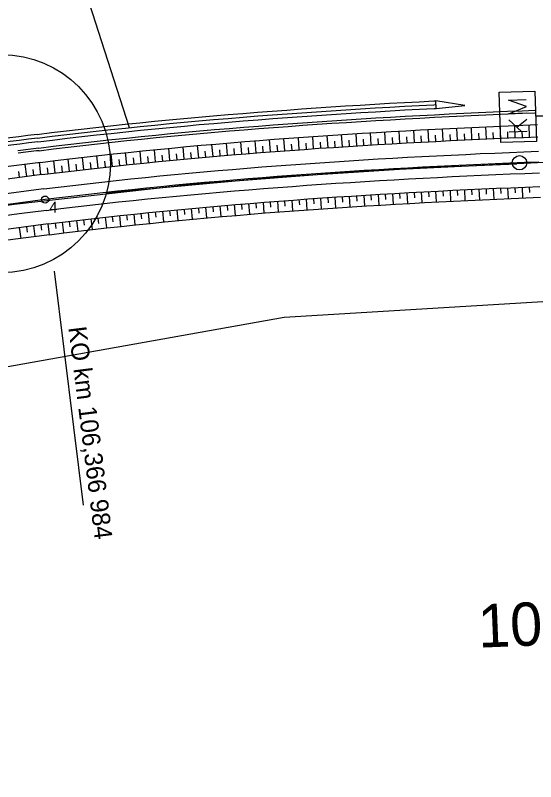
# Model space of a CAD drawing. Extents: x -759005 to -757278, y -1175311 to -1173953.
# Drawn here: x -758243.6 to -758207.5, y -1174807.5 to -1174754.3 of the extents above; entities that cross this region are included whole.
import ezdxf

# ---------------------------------------------------------------- set-up
doc = ezdxf.new("R2010")
doc.units = 0
for name, color, linetype in [('_NOR-návrh tenká', 7, 'Continuous'), ('_NOR-osa', 7, 'Continuous'), ('_NOR-popis', 7, 'Continuous'), ('_NOR-svahy', 7, 'Continuous'), ('_NOR-vytyčení', 7, 'Continuous'), ('G_Obvod stavby', 7, 'Continuous'), ('Vrstva 1', 7, 'Continuous'), ('Vrstva 52', 7, 'Continuous'), ('Vrstva 7', 7, 'Continuous')]:
    doc.layers.add(name, color=color, linetype=linetype)

# ---------------------------------------------------------------- blocks, each defined once
blk = doc.blocks.new('C020')
at = {"layer": 'Vrstva 7'}
for p, q in [((-1.017, 2.489), (-1.017, 1.242)), ((-0.182, 2.489), (-1.017, 1.654)), ((-0.713, 1.959), (-0.182, 1.242)), ((0, 0), (0, 0.623))]:
    blk.add_line(p, q, dxfattribs=at)
blk.add_lwpolyline([(-1.742, 0.623), (-1.742, 3.106), (1.746, 3.106), (1.746, 0.623)], close=True, dxfattribs=at)
blk.add_lwpolyline([(0.23, 1.242), (0.23, 2.489), (0.711, 1.242), (1.182, 2.489), (1.182, 1.242)], dxfattribs=at)
blk = doc.blocks.new('POINT_DISPLAY')
blk.add_line((0, 0), (0, 0))

msp = doc.modelspace()

# ---------------------------------------------------------------- linework, layer by layer
at = {"layer": '_NOR-návrh tenká'}
for p, q in [((-758214.421, -1174760.78), (-758214.447, -1174760.26)), ((-758212.435, -1174760.572), (-758214.447, -1174760.26)), ((-758214.421, -1174760.78), (-758212.435, -1174760.572))]:
    msp.add_line(p, q, dxfattribs=at)
for points in [[(-758242.105, -1174762.587), (-758241.09, -1174762.463), (-758240.072, -1174762.341), (-758239.053, -1174762.223), (-758238.033, -1174762.108), (-758237.014, -1174761.997), (-758235.995, -1174761.888), (-758234.975, -1174761.783), (-758233.956, -1174761.681), (-758232.936, -1174761.583), (-758231.917, -1174761.487), (-758230.897, -1174761.394), (-758229.877, -1174761.304), (-758228.858, -1174761.217), (-758227.838, -1174761.133), (-758226.819, -1174761.052), (-758225.799, -1174760.973), (-758224.78, -1174760.897), (-758223.76, -1174760.823), (-758222.741, -1174760.752), (-758221.722, -1174760.684), (-758220.703, -1174760.617), (-758219.684, -1174760.554), (-758218.665, -1174760.492), (-758217.646, -1174760.433), (-758216.627, -1174760.375), (-758215.609, -1174760.32), (-758214.59, -1174760.267), (-758214.447, -1174760.26)], [(-758242.073, -1174762.845), (-758241.059, -1174762.721), (-758240.041, -1174762.599), (-758239.023, -1174762.481), (-758238.005, -1174762.366), (-758236.986, -1174762.255), (-758235.968, -1174762.147), (-758234.949, -1174762.042), (-758233.93, -1174761.94), (-758232.912, -1174761.842), (-758231.893, -1174761.746), (-758230.874, -1174761.653), (-758229.855, -1174761.563), (-758228.836, -1174761.476), (-758227.817, -1174761.392), (-758226.798, -1174761.311), (-758225.78, -1174761.232), (-758224.761, -1174761.156), (-758223.742, -1174761.083), (-758222.723, -1174761.012), (-758221.705, -1174760.943), (-758220.686, -1174760.877), (-758219.668, -1174760.813), (-758218.649, -1174760.752), (-758217.631, -1174760.692), (-758216.613, -1174760.635), (-758215.595, -1174760.58), (-758214.577, -1174760.527), (-758214.434, -1174760.52)], [(-758242.041, -1174763.103), (-758241.028, -1174762.979), (-758240.011, -1174762.857), (-758238.994, -1174762.739), (-758237.976, -1174762.625), (-758236.958, -1174762.514), (-758235.941, -1174762.406), (-758234.923, -1174762.301), (-758233.905, -1174762.199), (-758232.887, -1174762.1), (-758231.869, -1174762.005), (-758230.851, -1174761.912), (-758229.833, -1174761.822), (-758228.814, -1174761.736), (-758227.796, -1174761.651), (-758226.778, -1174761.57), (-758225.76, -1174761.491), (-758224.742, -1174761.415), (-758223.724, -1174761.342), (-758222.705, -1174761.271), (-758221.687, -1174761.202), (-758220.67, -1174761.136), (-758219.652, -1174761.073), (-758218.634, -1174761.011), (-758217.616, -1174760.952), (-758216.599, -1174760.895), (-758215.581, -1174760.84), (-758214.564, -1174760.787), (-758214.421, -1174760.78)], [(-758241.988, -1174763.537), (-758240.975, -1174763.413), (-758239.96, -1174763.291), (-758238.944, -1174763.174), (-758237.928, -1174763.059), (-758236.912, -1174762.948), (-758235.895, -1174762.84), (-758234.879, -1174762.735), (-758233.862, -1174762.634), (-758232.845, -1174762.535), (-758231.829, -1174762.44), (-758230.812, -1174762.347), (-758229.795, -1174762.258), (-758228.778, -1174762.171), (-758227.761, -1174762.087), (-758226.744, -1174762.006), (-758225.727, -1174761.927), (-758224.71, -1174761.851), (-758223.693, -1174761.778), (-758222.676, -1174761.707), (-758221.659, -1174761.639), (-758220.642, -1174761.572), (-758219.625, -1174761.509), (-758218.608, -1174761.447), (-758217.591, -1174761.388), (-758216.575, -1174761.331), (-758215.558, -1174761.276), (-758214.542, -1174761.223), (-758213.525, -1174761.172), (-758212.509, -1174761.123), (-758211.493, -1174761.076), (-758210.477, -1174761.031), (-758209.461, -1174760.987), (-758208.445, -1174760.945), (-758207.581, -1174760.911)], [(-758241.966, -1174763.716), (-758240.954, -1174763.591), (-758239.939, -1174763.47), (-758238.923, -1174763.352), (-758237.908, -1174763.238), (-758236.892, -1174763.127), (-758235.877, -1174763.019), (-758234.861, -1174762.915), (-758233.845, -1174762.813), (-758232.828, -1174762.715), (-758231.812, -1174762.619), (-758230.796, -1174762.527), (-758229.779, -1174762.437), (-758228.763, -1174762.35), (-758227.746, -1174762.266), (-758226.73, -1174762.185), (-758225.713, -1174762.107), (-758224.696, -1174762.031), (-758223.68, -1174761.957), (-758222.663, -1174761.887), (-758221.647, -1174761.818), (-758220.63, -1174761.752), (-758219.614, -1174761.688), (-758218.597, -1174761.627), (-758217.581, -1174761.568), (-758216.565, -1174761.511), (-758215.548, -1174761.456), (-758214.532, -1174761.403), (-758213.516, -1174761.352), (-758212.5, -1174761.303), (-758211.484, -1174761.256), (-758210.469, -1174761.211), (-758209.453, -1174761.167), (-758208.438, -1174761.125), (-758207.573, -1174761.091)], [(-758241.865, -1174764.529), (-758240.855, -1174764.405), (-758239.843, -1174764.285), (-758238.83, -1174764.167), (-758237.818, -1174764.053), (-758236.804, -1174763.942), (-758235.791, -1174763.835), (-758234.778, -1174763.73), (-758233.764, -1174763.629), (-758232.75, -1174763.531), (-758231.737, -1174763.436), (-758230.723, -1174763.343), (-758229.708, -1174763.254), (-758228.694, -1174763.168), (-758227.68, -1174763.084), (-758226.665, -1174763.003), (-758225.651, -1174762.924), (-758224.636, -1174762.849), (-758223.622, -1174762.775), (-758222.607, -1174762.705), (-758221.593, -1174762.636), (-758220.578, -1174762.57), (-758219.563, -1174762.507), (-758218.549, -1174762.446), (-758217.534, -1174762.386), (-758216.52, -1174762.33), (-758215.505, -1174762.275), (-758214.49, -1174762.222), (-758213.476, -1174762.171), (-758212.462, -1174762.122), (-758211.447, -1174762.075), (-758210.433, -1174762.03), (-758209.419, -1174761.986), (-758208.404, -1174761.945), (-758207.39, -1174761.905)], [(-758241.761, -1174765.373), (-758240.753, -1174765.249), (-758239.744, -1174765.129), (-758238.734, -1174765.012), (-758237.724, -1174764.898), (-758236.713, -1174764.787), (-758235.703, -1174764.68), (-758234.692, -1174764.576), (-758233.681, -1174764.475), (-758232.67, -1174764.377), (-758231.658, -1174764.282), (-758230.647, -1174764.19), (-758229.635, -1174764.101), (-758228.623, -1174764.015), (-758227.611, -1174763.931), (-758226.599, -1174763.85), (-758225.587, -1174763.772), (-758224.574, -1174763.696), (-758223.562, -1174763.623), (-758222.549, -1174763.553), (-758221.537, -1174763.485), (-758220.524, -1174763.419), (-758219.511, -1174763.355), (-758218.498, -1174763.294), (-758217.486, -1174763.235), (-758216.473, -1174763.178), (-758215.46, -1174763.123), (-758214.447, -1174763.071), (-758213.434, -1174763.02), (-758212.421, -1174762.971), (-758211.409, -1174762.924), (-758210.396, -1174762.879), (-758209.383, -1174762.836), (-758208.37, -1174762.794), (-758207.357, -1174762.754)], [(-758241.638, -1174766.365), (-758240.633, -1174766.242), (-758239.627, -1174766.122), (-758238.62, -1174766.005), (-758237.613, -1174765.892), (-758236.606, -1174765.782), (-758235.599, -1174765.675), (-758234.591, -1174765.571), (-758233.583, -1174765.47), (-758232.575, -1174765.373), (-758231.566, -1174765.278), (-758230.558, -1174765.186), (-758229.549, -1174765.097), (-758228.539, -1174765.011), (-758227.53, -1174764.928), (-758226.521, -1174764.847), (-758225.511, -1174764.769), (-758224.501, -1174764.694), (-758223.491, -1174764.621), (-758222.481, -1174764.55), (-758221.471, -1174764.482), (-758220.46, -1174764.417), (-758219.45, -1174764.353), (-758218.439, -1174764.292), (-758217.429, -1174764.233), (-758216.418, -1174764.177), (-758215.407, -1174764.122), (-758214.396, -1174764.069), (-758213.385, -1174764.019), (-758212.374, -1174763.97), (-758211.363, -1174763.923), (-758210.352, -1174763.878), (-758209.341, -1174763.835), (-758208.33, -1174763.793), (-758207.319, -1174763.753)], [(-758241.454, -1174767.854), (-758240.453, -1174767.731), (-758239.452, -1174767.612), (-758238.45, -1174767.496), (-758237.448, -1174767.383), (-758236.446, -1174767.273), (-758235.443, -1174767.167), (-758234.44, -1174767.063), (-758233.436, -1174766.963), (-758232.432, -1174766.866), (-758231.428, -1174766.771), (-758230.424, -1174766.68), (-758229.419, -1174766.592), (-758228.414, -1174766.506), (-758227.409, -1174766.423), (-758226.403, -1174766.342), (-758225.397, -1174766.265), (-758224.391, -1174766.19), (-758223.385, -1174766.117), (-758222.378, -1174766.047), (-758221.372, -1174765.979), (-758220.365, -1174765.914), (-758219.358, -1174765.851), (-758218.35, -1174765.79), (-758217.343, -1174765.731), (-758216.335, -1174765.674), (-758215.328, -1174765.62), (-758214.32, -1174765.567), (-758213.312, -1174765.517), (-758212.303, -1174765.468), (-758211.295, -1174765.422), (-758210.287, -1174765.377), (-758209.278, -1174765.333), (-758208.269, -1174765.292), (-758207.261, -1174765.252)], [(-758241.337, -1174768.797), (-758240.338, -1174768.674), (-758239.341, -1174768.555), (-758238.342, -1174768.439), (-758237.343, -1174768.327), (-758236.344, -1174768.218), (-758235.344, -1174768.111), (-758234.344, -1174768.008), (-758233.343, -1174767.908), (-758232.342, -1174767.811), (-758231.341, -1174767.717), (-758230.339, -1174767.626), (-758229.337, -1174767.538), (-758228.334, -1174767.452), (-758227.332, -1174767.37), (-758226.329, -1174767.29), (-758225.325, -1174767.212), (-758224.322, -1174767.137), (-758223.318, -1174767.065), (-758222.313, -1174766.995), (-758221.309, -1174766.927), (-758220.304, -1174766.862), (-758219.299, -1174766.799), (-758218.294, -1174766.738), (-758217.289, -1174766.679), (-758216.283, -1174766.623), (-758215.277, -1174766.569), (-758214.271, -1174766.516), (-758213.265, -1174766.466), (-758212.258, -1174766.417), (-758211.252, -1174766.371), (-758210.245, -1174766.326), (-758209.238, -1174766.283), (-758208.231, -1174766.241), (-758207.224, -1174766.201)], [(-758241.245, -1174769.541), (-758240.248, -1174769.419), (-758239.253, -1174769.3), (-758238.257, -1174769.185), (-758237.26, -1174769.072), (-758236.263, -1174768.963), (-758235.266, -1174768.857), (-758234.268, -1174768.755), (-758233.27, -1174768.655), (-758232.271, -1174768.558), (-758231.272, -1174768.464), (-758230.272, -1174768.373), (-758229.272, -1174768.285), (-758228.272, -1174768.2), (-758227.271, -1174768.117), (-758226.27, -1174768.037), (-758225.268, -1174767.96), (-758224.267, -1174767.885), (-758223.265, -1174767.813), (-758222.262, -1174767.743), (-758221.259, -1174767.675), (-758220.256, -1174767.61), (-758219.253, -1174767.547), (-758218.25, -1174767.487), (-758217.246, -1174767.428), (-758216.242, -1174767.372), (-758215.237, -1174767.318), (-758214.233, -1174767.265), (-758213.228, -1174767.215), (-758212.223, -1174767.166), (-758211.218, -1174767.12), (-758210.212, -1174767.075), (-758209.207, -1174767.032), (-758208.201, -1174766.991), (-758207.195, -1174766.951)]]:
    msp.add_lwpolyline(points, dxfattribs=at)
for radius, start, end in [(297.557, 97.09744, 101.02201), (297.297, 97.09748, 101.02201), (297.037, 97.09752, 101.02201), (296.6, 97.09759, 97.37991), (296.42, 97.09762, 97.38099), (295.6, 97.09776, 129.28488), (294.75, 97.0979, 129.28474), (293.75, 97.09807, 120.96729), (292.25, 97.09832, 120.96729), (291.3, 97.09848, 129.28417), (290.55, 97.09861, 129.28404)]:
    msp.add_arc((-758205.34, -1175057.864), radius, start, end, dxfattribs=at)
at = {"layer": '_NOR-osa'}
msp.add_lwpolyline([(-758207.29, -1174764.503), (-758208.3, -1174764.543), (-758209.31, -1174764.584), (-758210.319, -1174764.627), (-758211.329, -1174764.672), (-758212.339, -1174764.719), (-758213.348, -1174764.768), (-758214.358, -1174764.818), (-758215.367, -1174764.871), (-758216.377, -1174764.926), (-758217.386, -1174764.982), (-758218.395, -1174765.041), (-758219.404, -1174765.102), (-758220.412, -1174765.165), (-758221.421, -1174765.231), (-758222.43, -1174765.299), (-758223.438, -1174765.369), (-758224.446, -1174765.442), (-758225.454, -1174765.517), (-758226.462, -1174765.595), (-758227.469, -1174765.675), (-758228.477, -1174765.758), (-758229.484, -1174765.844), (-758230.491, -1174765.933), (-758231.497, -1174766.025), (-758232.504, -1174766.119), (-758233.51, -1174766.217), (-758234.515, -1174766.317), (-758235.521, -1174766.421), (-758236.526, -1174766.527), (-758237.531, -1174766.637), (-758238.535, -1174766.75), (-758239.539, -1174766.867), (-758240.543, -1174766.987), (-758241.546, -1174767.11)], dxfattribs=at)
msp.add_circle((-758241.546, -1174767.11), 0.25, dxfattribs=at)
msp.add_arc((-758205.34, -1175057.864), 293, 97.09819, 129.28445, dxfattribs=at)
at = {"layer": '_NOR-popis'}
msp.add_line((-758240.928, -1174772.071), (-758238.907, -1174788.304), dxfattribs=at)
msp.add_lwpolyline([(-758240.814, -1174715.275), (-758249.857, -1174718.187), (-758235.706, -1174762.12)], dxfattribs=at)
msp.add_circle((-758208.639, -1174764.556), 0.5, dxfattribs=at)
at = {"layer": '_NOR-svahy'}
for points in [[(-758213.935, -1174763.045), (-758213.977, -1174762.196)], [(-758212.936, -1174762.996), (-758212.977, -1174762.147)], [(-758211.937, -1174762.949), (-758211.976, -1174762.1)], [(-758210.938, -1174762.903), (-758210.976, -1174762.054)], [(-758209.939, -1174762.859), (-758209.975, -1174762.01)], [(-758208.94, -1174762.817), (-758208.975, -1174761.968)], [(-758207.941, -1174762.777), (-758207.974, -1174761.928)], [(-758222.919, -1174763.578), (-758222.978, -1174762.73)], [(-758221.921, -1174763.51), (-758221.978, -1174762.662)], [(-758220.923, -1174763.445), (-758220.978, -1174762.596)], [(-758219.925, -1174763.381), (-758219.978, -1174762.533)], [(-758218.927, -1174763.32), (-758218.978, -1174762.472)], [(-758217.929, -1174763.261), (-758217.978, -1174762.412)], [(-758216.93, -1174763.204), (-758216.978, -1174762.355)], [(-758216.431, -1174763.176), (-758216.454, -1174762.752)], [(-758215.932, -1174763.149), (-758215.978, -1174762.3)], [(-758215.433, -1174763.122), (-758215.455, -1174762.698)], [(-758214.933, -1174763.096), (-758214.977, -1174762.247)], [(-758214.434, -1174763.07), (-758214.455, -1174762.646)], [(-758213.435, -1174763.02), (-758213.457, -1174762.596)], [(-758212.436, -1174762.972), (-758212.457, -1174762.547)], [(-758211.437, -1174762.926), (-758211.457, -1174762.501)], [(-758210.438, -1174762.881), (-758210.457, -1174762.456)], [(-758209.439, -1174762.838), (-758209.458, -1174762.413)], [(-758208.44, -1174762.797), (-758208.458, -1174762.372)], [(-758229.897, -1174764.124), (-758229.972, -1174763.277)], [(-758228.901, -1174764.038), (-758228.973, -1174763.191)], [(-758227.904, -1174763.955), (-758227.974, -1174763.108)], [(-758226.908, -1174763.875), (-758226.975, -1174763.027)], [(-758225.911, -1174763.797), (-758225.976, -1174762.949)], [(-758224.914, -1174763.722), (-758224.977, -1174762.874)], [(-758224.415, -1174763.685), (-758224.445, -1174763.261)], [(-758223.916, -1174763.649), (-758223.977, -1174762.801)], [(-758223.417, -1174763.613), (-758223.447, -1174763.189)], [(-758222.42, -1174763.544), (-758222.448, -1174763.12)], [(-758221.422, -1174763.477), (-758221.45, -1174763.053)], [(-758220.424, -1174763.412), (-758220.451, -1174762.988)], [(-758219.426, -1174763.35), (-758219.452, -1174762.926)], [(-758218.428, -1174763.29), (-758218.453, -1174762.866)], [(-758217.43, -1174763.232), (-758217.453, -1174762.808)], [(-758234.875, -1174764.595), (-758234.962, -1174763.749)], [(-758233.88, -1174764.495), (-758233.965, -1174763.649)], [(-758232.885, -1174764.398), (-758232.967, -1174763.552)], [(-758231.889, -1174764.304), (-758231.969, -1174763.457)], [(-758230.893, -1174764.212), (-758230.97, -1174763.366)], [(-758230.395, -1174764.168), (-758230.433, -1174763.745)], [(-758229.399, -1174764.081), (-758229.435, -1174763.657)], [(-758228.403, -1174763.996), (-758228.438, -1174763.573)], [(-758227.406, -1174763.915), (-758227.44, -1174763.491)], [(-758226.409, -1174763.835), (-758226.442, -1174763.412)], [(-758225.412, -1174763.759), (-758225.444, -1174763.335)], [(-758239.845, -1174765.141), (-758239.946, -1174764.297)], [(-758238.852, -1174765.025), (-758238.95, -1174764.181)], [(-758237.858, -1174764.913), (-758237.953, -1174764.068)], [(-758236.864, -1174764.804), (-758236.956, -1174763.959)], [(-758236.367, -1174764.751), (-758236.412, -1174764.328)], [(-758235.87, -1174764.698), (-758235.959, -1174763.853)], [(-758235.372, -1174764.646), (-758235.416, -1174764.223)], [(-758234.378, -1174764.545), (-758234.42, -1174764.122)], [(-758233.382, -1174764.446), (-758233.423, -1174764.023)], [(-758232.387, -1174764.35), (-758232.427, -1174763.927)], [(-758231.391, -1174764.258), (-758231.43, -1174763.835)], [(-758242.823, -1174765.507), (-758242.931, -1174764.664)], [(-758241.83, -1174765.382), (-758241.936, -1174764.538)], [(-758240.838, -1174765.26), (-758240.942, -1174764.416)], [(-758240.342, -1174765.2), (-758240.392, -1174764.778)], [(-758239.348, -1174765.083), (-758239.397, -1174764.661)], [(-758238.355, -1174764.969), (-758238.402, -1174764.547)], [(-758237.361, -1174764.858), (-758237.407, -1174764.436)], [(-758243.318, -1174765.571), (-758243.373, -1174765.15)], [(-758242.327, -1174765.444), (-758242.38, -1174765.022)], [(-758241.334, -1174765.321), (-758241.386, -1174764.899)], [(-758213.457, -1174766.475), (-758213.42, -1174767.225)], [(-758212.958, -1174766.451), (-758212.94, -1174766.826)], [(-758212.458, -1174766.427), (-758212.422, -1174767.176)], [(-758211.959, -1174766.403), (-758211.942, -1174766.778)], [(-758211.459, -1174766.38), (-758211.425, -1174767.129)], [(-758210.96, -1174766.358), (-758210.943, -1174766.732)], [(-758210.46, -1174766.335), (-758210.427, -1174767.085)], [(-758209.961, -1174766.314), (-758209.945, -1174766.688)], [(-758209.461, -1174766.292), (-758209.429, -1174767.041)], [(-758208.962, -1174766.271), (-758208.946, -1174766.646)], [(-758208.462, -1174766.251), (-758208.431, -1174767)], [(-758207.963, -1174766.231), (-758207.948, -1174766.605)], [(-758222.442, -1174767.004), (-758222.389, -1174767.752)], [(-758221.943, -1174766.97), (-758221.917, -1174767.344)], [(-758221.444, -1174766.936), (-758221.393, -1174767.684)], [(-758220.945, -1174766.903), (-758220.921, -1174767.278)], [(-758220.446, -1174766.871), (-758220.397, -1174767.619)], [(-758219.947, -1174766.839), (-758219.923, -1174767.214)], [(-758219.448, -1174766.808), (-758219.401, -1174767.557)], [(-758218.949, -1174766.778), (-758218.926, -1174767.152)], [(-758218.45, -1174766.747), (-758218.404, -1174767.496)], [(-758217.951, -1174766.718), (-758217.929, -1174767.092)], [(-758217.451, -1174766.689), (-758217.408, -1174767.438)], [(-758216.952, -1174766.661), (-758216.931, -1174767.035)], [(-758216.453, -1174766.633), (-758216.411, -1174767.381)], [(-758215.954, -1174766.605), (-758215.934, -1174766.98)], [(-758215.455, -1174766.578), (-758215.414, -1174767.327)], [(-758214.955, -1174766.552), (-758214.936, -1174766.926)], [(-758214.456, -1174766.526), (-758214.417, -1174767.275)], [(-758213.957, -1174766.5), (-758213.938, -1174766.875)], [(-758229.42, -1174767.545), (-758229.355, -1174768.292)], [(-758228.922, -1174767.503), (-758228.89, -1174767.876)], [(-758228.424, -1174767.46), (-758228.36, -1174768.207)], [(-758227.926, -1174767.419), (-758227.895, -1174767.792)], [(-758227.427, -1174767.378), (-758227.366, -1174768.125)], [(-758226.929, -1174767.337), (-758226.899, -1174767.711)], [(-758226.431, -1174767.298), (-758226.371, -1174768.045)], [(-758225.932, -1174767.259), (-758225.903, -1174767.633)], [(-758225.434, -1174767.22), (-758225.376, -1174767.968)], [(-758224.935, -1174767.183), (-758224.907, -1174767.557)], [(-758224.436, -1174767.146), (-758224.381, -1174767.894)], [(-758223.938, -1174767.109), (-758223.911, -1174767.483)], [(-758223.439, -1174767.073), (-758223.385, -1174767.821)], [(-758222.94, -1174767.038), (-758222.914, -1174767.412)], [(-758234.896, -1174768.065), (-758234.857, -1174768.438)], [(-758234.398, -1174768.014), (-758234.322, -1174768.76)], [(-758233.901, -1174767.964), (-758233.864, -1174768.337)], [(-758233.403, -1174767.914), (-758233.329, -1174768.661)], [(-758232.906, -1174767.866), (-758232.87, -1174768.239)], [(-758232.408, -1174767.818), (-758232.336, -1174768.564)], [(-758231.91, -1174767.771), (-758231.875, -1174768.144)], [(-758231.412, -1174767.724), (-758231.342, -1174768.471)], [(-758230.914, -1174767.679), (-758230.881, -1174768.052)], [(-758230.417, -1174767.633), (-758230.349, -1174768.38)], [(-758229.918, -1174767.589), (-758229.886, -1174767.963)], [(-758239.369, -1174768.558), (-758239.28, -1174769.303)], [(-758238.872, -1174768.501), (-758238.829, -1174768.873)], [(-758238.375, -1174768.443), (-758238.289, -1174769.188)], [(-758237.878, -1174768.387), (-758237.836, -1174768.76)], [(-758237.382, -1174768.331), (-758237.298, -1174769.076)], [(-758236.885, -1174768.277), (-758236.844, -1174768.649)], [(-758236.387, -1174768.222), (-758236.306, -1174768.968)], [(-758235.89, -1174768.169), (-758235.851, -1174768.542)], [(-758235.393, -1174768.117), (-758235.314, -1174768.862)], [(-758243.338, -1174769.053), (-758243.24, -1174769.797)], [(-758242.842, -1174768.988), (-758242.794, -1174769.36)], [(-758242.346, -1174768.924), (-758242.251, -1174769.668)], [(-758241.85, -1174768.861), (-758241.803, -1174769.233)], [(-758241.354, -1174768.799), (-758241.261, -1174769.543)], [(-758240.858, -1174768.738), (-758240.812, -1174769.11)], [(-758240.362, -1174768.677), (-758240.27, -1174769.421)], [(-758239.865, -1174768.618), (-758239.821, -1174768.99)]]:
    msp.add_lwpolyline(points, dxfattribs=at)
at = {"layer": 'G_Obvod stavby'}
msp.add_lwpolyline([(-758392.72, -1174840.756), (-758391.23, -1174838.56), (-758368.37, -1174821.64), (-758340.31, -1174807.33), (-758320.27, -1174796.89), (-758301, -1174790.21), (-758267.96, -1174782.93), (-758224.96, -1174775.27), (-758184.87, -1174772.83), (-758142.71, -1174770.26), (-758089.84, -1174768.68), (-758106.02, -1174731.44), (-758149.09, -1174725.67), (-758199.62, -1174726.6), (-758225.76, -1174732.36), (-758252.17, -1174738.18), (-758254.97, -1174739.34), (-758266.58, -1174744.16), (-758279.45, -1174749.49), (-758302.42, -1174759.02), (-758331.68, -1174770.24), (-758367.17, -1174799.81), (-758405.64, -1174832.2)], dxfattribs=at)
at = {"layer": 'Vrstva 1'}
for points in [[(-758275.047, -1174773.289), (-758265.484, -1174771.118), (-758253.61, -1174768.888), (-758243.69, -1174767.426), (-758231.371, -1174766.042), (-758219.363, -1174765.122), (-758206.915, -1174764.505), (-758194.225, -1174764.118), (-758182.013, -1174763.871), (-758170.862, -1174763.683), (-758162.019, -1174763.496), (-758153.195, -1174763.228), (-758152.069, -1174763.19), (-758141.836, -1174762.716), (-758130.402, -1174761.933), (-758120.726, -1174760.981), (-758108.612, -1174759.398), (-758096.467, -1174757.277), (-758085.591, -1174754.917)], [(-758237.305, -1174766.709), (-758231.371, -1174766.042), (-758219.363, -1174765.122), (-758206.915, -1174764.505), (-758205.8, -1174764.471)], [(-758237.292, -1174766.663), (-758236.119, -1174766.52), (-758225.849, -1174765.581), (-758215.553, -1174764.913), (-758208.822, -1174764.637)]]:
    msp.add_lwpolyline(points, dxfattribs=at)
at = {"layer": 'Vrstva 52'}
msp.add_circle((-758244.571, -1174764.621), 7.56, dxfattribs=at)
msp.add_circle((-758244.571, -1174764.621), 7.56, dxfattribs=at)

# ---------------------------------------------------------------- block references
at = {"layer": '_NOR-vytyčení'}
msp.add_blockref('POINT_DISPLAY', (-758241.546, -1174767.11), dxfattribs=at)
at = {"layer": 'Vrstva 7', "rotation": 91.74677671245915}
msp.add_blockref('C020', (-758206.89, -1174761.314), dxfattribs=at)

# ---------------------------------------------------------------- texts
at = {"layer": '_NOR-popis'}
for s, height, rotation, p in [('KO km 106,366 984', 1.25, 277.0982, (-758239.938, -1174775.979)), ('106,4', 3, 2.3427, (-758211.462, -1174798.184))]:
    msp.add_text(s, height=height, rotation=rotation, dxfattribs=at).set_placement(p)
at = {"layer": '_NOR-vytyčení'}
msp.add_text('4', height=0.75, rotation=360, dxfattribs=at).set_placement((-758241.246, -1174768.01))

doc.saveas('drawing.dxf')
